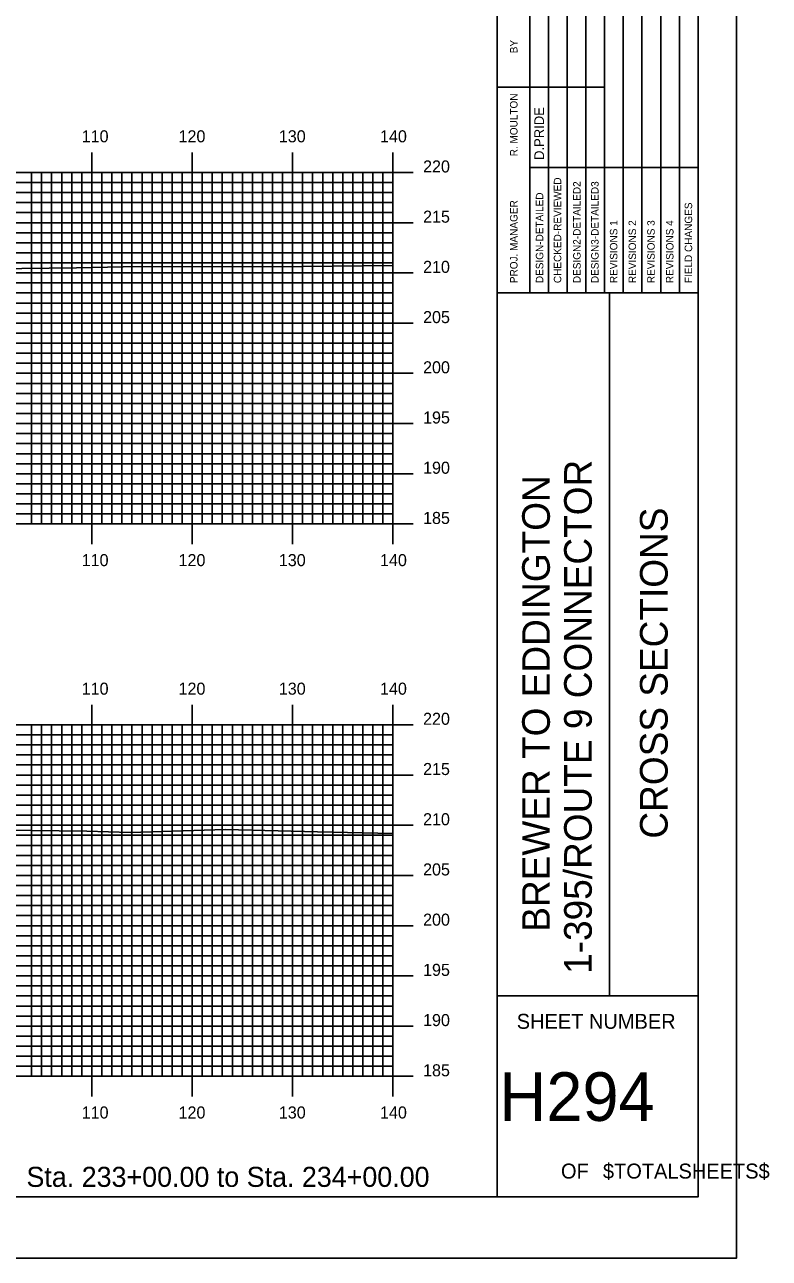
# Model space of a CAD drawing. Extents: x 1799962 to 1800305, y 442591 to 442811.
# Drawn here: x 1800230.8 to 1800305, y 442590.5 to 442713.4 of the extents above; entities that cross this region are included whole.
import ezdxf

# ---------------------------------------------------------------- set-up
doc = ezdxf.new("R2010")
doc.units = 0
for name, color, linetype in [('BORDER', 7, 'Continuous'), ('H_V ANNOTATION', 7, 'Continuous'), ('MAJOR', 7, 'Continuous'), ('MINOR', 7, 'Continuous'), ('PLOT BOUNDARY', 7, 'Continuous'), ('S_Roadway_Centerline', 7, 'Continuous')]:
    doc.layers.add(name, color=color, linetype=linetype)

msp = doc.modelspace()

# ---------------------------------------------------------------- linework, layer by layer
at = {"layer": 'BORDER'}
for p, q in [((1800277.92, 442596.67), (1800277.92, 442806.67)), ((1800277.92, 442686.67), (1800297.92, 442686.67)), ((1800289.11, 442616.67), (1800289.11, 442686.67)), ((1800277.92, 442616.67), (1800297.92, 442616.67))]:
    msp.add_line(p, q, dxfattribs=at)
msp.add_lwpolyline([(1799977.92, 442596.67), (1800297.92, 442596.67), (1800297.92, 442806.67), (1799977.92, 442806.67)], close=True, dxfattribs=at)
for points in [[(1800283.02, 442686.68), (1800283.02, 442721.67)], [(1800284.88, 442721.67), (1800284.88, 442686.68)], [(1800286.74, 442686.68), (1800286.74, 442721.67)], [(1800288.61, 442686.68), (1800288.61, 442721.67)], [(1800290.47, 442686.68), (1800290.47, 442721.67)], [(1800292.33, 442686.68), (1800292.33, 442721.67)], [(1800294.2, 442686.68), (1800294.2, 442721.67)], [(1800296.06, 442686.68), (1800296.06, 442721.67)], [(1800281.15, 442686.68), (1800281.15, 442720.26)], [(1800277.92, 442707.17), (1800281.15, 442707.17)], [(1800281.15, 442707.17), (1800288.61, 442707.17)], [(1800281.15, 442699.17), (1800297.92, 442699.17)]]:
    msp.add_lwpolyline(points, dxfattribs=at)
at = {"layer": 'MAJOR'}
for p, q in [((1800237.52, 442700.67), (1800237.52, 442698.67)), ((1800247.52, 442700.67), (1800247.52, 442698.67)), ((1800257.52, 442700.67), (1800257.52, 442698.67)), ((1800267.52, 442700.67), (1800267.52, 442698.67)), ((1799987.52, 442698.67), (1800267.52, 442698.67)), ((1799987.52, 442698.67), (1800267.52, 442698.67)), ((1800237.52, 442663.67), (1800237.52, 442698.67)), ((1800247.52, 442663.67), (1800247.52, 442698.67)), ((1800257.52, 442663.67), (1800257.52, 442698.67)), ((1800269.53, 442698.67), (1800265.52, 442698.67)), ((1800267.52, 442663.67), (1800267.52, 442698.67)), ((1800267.52, 442663.67), (1800267.52, 442698.67)), ((1799987.52, 442693.67), (1800267.52, 442693.67)), ((1800269.53, 442693.67), (1800265.52, 442693.67)), ((1799987.52, 442688.67), (1800267.52, 442688.67)), ((1800269.53, 442688.67), (1800265.52, 442688.67)), ((1799987.52, 442683.67), (1800267.52, 442683.67)), ((1800269.53, 442683.67), (1800265.52, 442683.67)), ((1799987.52, 442678.67), (1800267.52, 442678.67)), ((1800269.53, 442678.67), (1800265.52, 442678.67)), ((1799987.52, 442673.67), (1800267.52, 442673.67)), ((1800269.53, 442673.67), (1800265.52, 442673.67)), ((1799987.52, 442668.67), (1800267.52, 442668.67)), ((1800269.53, 442668.67), (1800265.52, 442668.67)), ((1799987.52, 442663.67), (1800267.52, 442663.67)), ((1799987.52, 442663.67), (1800267.52, 442663.67)), ((1800237.52, 442661.66), (1800237.52, 442663.67)), ((1800247.52, 442661.66), (1800247.52, 442663.67)), ((1800257.52, 442661.66), (1800257.52, 442663.67)), ((1800269.53, 442663.67), (1800265.52, 442663.67)), ((1800267.52, 442661.66), (1800267.52, 442663.67)), ((1800237.52, 442645.67), (1800237.52, 442643.67)), ((1800247.52, 442645.67), (1800247.52, 442643.67)), ((1800257.52, 442645.67), (1800257.52, 442643.67)), ((1800267.52, 442645.67), (1800267.52, 442643.67)), ((1799987.52, 442643.67), (1800267.52, 442643.67)), ((1799987.52, 442643.67), (1800267.52, 442643.67)), ((1800237.52, 442608.67), (1800237.52, 442643.67)), ((1800247.52, 442608.67), (1800247.52, 442643.67)), ((1800257.52, 442608.67), (1800257.52, 442643.67)), ((1800269.53, 442643.67), (1800265.52, 442643.67)), ((1800267.52, 442608.67), (1800267.52, 442643.67)), ((1800267.52, 442608.67), (1800267.52, 442643.67)), ((1799987.52, 442638.67), (1800267.52, 442638.67)), ((1800269.53, 442638.67), (1800265.52, 442638.67)), ((1799987.52, 442633.67), (1800267.52, 442633.67)), ((1800269.53, 442633.67), (1800265.52, 442633.67)), ((1799987.52, 442628.67), (1800267.52, 442628.67)), ((1800269.53, 442628.67), (1800265.52, 442628.67)), ((1799987.52, 442623.67), (1800267.52, 442623.67)), ((1800269.53, 442623.67), (1800265.52, 442623.67)), ((1799987.52, 442618.67), (1800267.52, 442618.67)), ((1800269.53, 442618.67), (1800265.52, 442618.67)), ((1799987.52, 442613.67), (1800267.52, 442613.67)), ((1800269.53, 442613.67), (1800265.52, 442613.67)), ((1799987.52, 442608.67), (1800267.52, 442608.67)), ((1799987.52, 442608.67), (1800267.52, 442608.67)), ((1800237.52, 442606.66), (1800237.52, 442608.67)), ((1800247.52, 442606.66), (1800247.52, 442608.67)), ((1800257.52, 442606.66), (1800257.52, 442608.67)), ((1800269.53, 442608.67), (1800265.52, 442608.67)), ((1800267.52, 442606.66), (1800267.52, 442608.67))]:
    msp.add_line(p, q, dxfattribs=at)
at = {"layer": 'MINOR'}
for p, q in [((1800231.52, 442663.67), (1800231.52, 442698.67)), ((1800232.52, 442663.67), (1800232.52, 442698.67)), ((1800233.52, 442663.67), (1800233.52, 442698.67)), ((1800234.52, 442663.67), (1800234.52, 442698.67)), ((1800235.52, 442663.67), (1800235.52, 442698.67)), ((1800236.52, 442663.67), (1800236.52, 442698.67)), ((1800238.52, 442663.67), (1800238.52, 442698.67)), ((1800239.52, 442663.67), (1800239.52, 442698.67)), ((1800240.52, 442663.67), (1800240.52, 442698.67)), ((1800241.52, 442663.67), (1800241.52, 442698.67)), ((1800242.52, 442663.67), (1800242.52, 442698.67)), ((1800243.52, 442663.67), (1800243.52, 442698.67)), ((1800244.52, 442663.67), (1800244.52, 442698.67)), ((1800245.52, 442663.67), (1800245.52, 442698.67)), ((1800246.52, 442663.67), (1800246.52, 442698.67)), ((1800248.52, 442663.67), (1800248.52, 442698.67)), ((1800249.52, 442663.67), (1800249.52, 442698.67)), ((1800250.52, 442663.67), (1800250.52, 442698.67)), ((1800251.52, 442663.67), (1800251.52, 442698.67)), ((1800252.52, 442663.67), (1800252.52, 442698.67)), ((1800253.52, 442663.67), (1800253.52, 442698.67)), ((1800254.52, 442663.67), (1800254.52, 442698.67)), ((1800255.52, 442663.67), (1800255.52, 442698.67)), ((1800256.52, 442663.67), (1800256.52, 442698.67)), ((1800258.52, 442663.67), (1800258.52, 442698.67)), ((1800259.52, 442663.67), (1800259.52, 442698.67)), ((1800260.52, 442663.67), (1800260.52, 442698.67)), ((1800261.52, 442663.67), (1800261.52, 442698.67)), ((1800262.52, 442663.67), (1800262.52, 442698.67)), ((1800263.52, 442663.67), (1800263.52, 442698.67)), ((1800264.52, 442663.67), (1800264.52, 442698.67)), ((1800265.52, 442663.67), (1800265.52, 442698.67)), ((1800266.52, 442663.67), (1800266.52, 442698.67)), ((1799987.52, 442697.67), (1800267.52, 442697.67)), ((1800267.52, 442697.67), (1800265.52, 442697.67)), ((1799987.52, 442696.67), (1800267.52, 442696.67)), ((1800267.52, 442696.67), (1800265.52, 442696.67)), ((1799987.52, 442695.67), (1800267.52, 442695.67)), ((1800267.52, 442695.67), (1800265.52, 442695.67)), ((1799987.52, 442694.67), (1800267.52, 442694.67)), ((1800267.52, 442694.67), (1800265.52, 442694.67)), ((1799987.52, 442692.67), (1800267.52, 442692.67)), ((1800267.52, 442692.67), (1800265.52, 442692.67)), ((1799987.52, 442691.67), (1800267.52, 442691.67)), ((1800267.52, 442691.67), (1800265.52, 442691.67)), ((1799987.52, 442690.67), (1800267.52, 442690.67)), ((1800267.52, 442690.67), (1800265.52, 442690.67)), ((1799987.52, 442689.67), (1800267.52, 442689.67)), ((1800267.52, 442689.67), (1800265.52, 442689.67)), ((1799987.52, 442687.67), (1800267.52, 442687.67)), ((1800267.52, 442687.67), (1800265.52, 442687.67)), ((1799987.52, 442686.67), (1800267.52, 442686.67)), ((1800267.52, 442686.67), (1800265.52, 442686.67)), ((1799987.52, 442685.67), (1800267.52, 442685.67)), ((1800267.52, 442685.67), (1800265.52, 442685.67)), ((1799987.52, 442684.67), (1800267.52, 442684.67)), ((1800267.52, 442684.67), (1800265.52, 442684.67)), ((1799987.52, 442682.67), (1800267.52, 442682.67)), ((1800267.52, 442682.67), (1800265.52, 442682.67)), ((1799987.52, 442681.67), (1800267.52, 442681.67)), ((1800267.52, 442681.67), (1800265.52, 442681.67)), ((1799987.52, 442680.67), (1800267.52, 442680.67)), ((1800267.52, 442680.67), (1800265.52, 442680.67)), ((1799987.52, 442679.67), (1800267.52, 442679.67)), ((1800267.52, 442679.67), (1800265.52, 442679.67)), ((1799987.52, 442677.67), (1800267.52, 442677.67)), ((1799987.52, 442676.67), (1800267.52, 442676.67)), ((1800267.52, 442677.67), (1800265.52, 442677.67)), ((1800267.52, 442676.67), (1800265.52, 442676.67)), ((1799987.52, 442675.67), (1800267.52, 442675.67)), ((1800267.52, 442675.67), (1800265.52, 442675.67)), ((1799987.52, 442674.67), (1800267.52, 442674.67)), ((1800267.52, 442674.67), (1800265.52, 442674.67)), ((1799987.52, 442672.67), (1800267.52, 442672.67)), ((1799987.52, 442671.67), (1800267.52, 442671.67)), ((1800267.52, 442672.67), (1800265.52, 442672.67)), ((1800267.52, 442671.67), (1800265.52, 442671.67)), ((1799987.52, 442670.67), (1800267.52, 442670.67)), ((1800267.52, 442670.67), (1800265.52, 442670.67)), ((1799987.52, 442669.67), (1800267.52, 442669.67)), ((1800267.52, 442669.67), (1800265.52, 442669.67)), ((1799987.52, 442667.67), (1800267.52, 442667.67)), ((1799987.52, 442666.67), (1800267.52, 442666.67)), ((1800267.52, 442667.67), (1800265.52, 442667.67)), ((1800267.52, 442666.67), (1800265.52, 442666.67)), ((1799987.52, 442665.67), (1800267.52, 442665.67)), ((1800267.52, 442665.67), (1800265.52, 442665.67)), ((1799987.52, 442664.67), (1800267.52, 442664.67)), ((1800267.52, 442664.67), (1800265.52, 442664.67)), ((1800231.52, 442608.67), (1800231.52, 442643.67)), ((1800232.52, 442608.67), (1800232.52, 442643.67)), ((1800233.52, 442608.67), (1800233.52, 442643.67)), ((1800234.52, 442608.67), (1800234.52, 442643.67)), ((1800235.52, 442608.67), (1800235.52, 442643.67)), ((1800236.52, 442608.67), (1800236.52, 442643.67)), ((1800238.52, 442608.67), (1800238.52, 442643.67)), ((1800239.52, 442608.67), (1800239.52, 442643.67)), ((1800240.52, 442608.67), (1800240.52, 442643.67)), ((1800241.52, 442608.67), (1800241.52, 442643.67)), ((1800242.52, 442608.67), (1800242.52, 442643.67)), ((1800243.52, 442608.67), (1800243.52, 442643.67)), ((1800244.52, 442608.67), (1800244.52, 442643.67)), ((1800245.52, 442608.67), (1800245.52, 442643.67)), ((1800246.52, 442608.67), (1800246.52, 442643.67)), ((1800248.52, 442608.67), (1800248.52, 442643.67)), ((1800249.52, 442608.67), (1800249.52, 442643.67)), ((1800250.52, 442608.67), (1800250.52, 442643.67)), ((1800251.52, 442608.67), (1800251.52, 442643.67)), ((1800252.52, 442608.67), (1800252.52, 442643.67)), ((1800253.52, 442608.67), (1800253.52, 442643.67)), ((1800254.52, 442608.67), (1800254.52, 442643.67)), ((1800255.52, 442608.67), (1800255.52, 442643.67)), ((1800256.52, 442608.67), (1800256.52, 442643.67)), ((1800258.52, 442608.67), (1800258.52, 442643.67)), ((1800259.52, 442608.67), (1800259.52, 442643.67)), ((1800260.52, 442608.67), (1800260.52, 442643.67)), ((1800261.52, 442608.67), (1800261.52, 442643.67)), ((1800262.52, 442608.67), (1800262.52, 442643.67)), ((1800263.52, 442608.67), (1800263.52, 442643.67)), ((1800264.52, 442608.67), (1800264.52, 442643.67)), ((1800265.52, 442608.67), (1800265.52, 442643.67)), ((1800266.52, 442608.67), (1800266.52, 442643.67)), ((1799987.52, 442642.67), (1800267.52, 442642.67)), ((1800267.52, 442642.67), (1800265.52, 442642.67)), ((1799987.52, 442641.67), (1800267.52, 442641.67)), ((1800267.52, 442641.67), (1800265.52, 442641.67)), ((1799987.52, 442640.67), (1800267.52, 442640.67)), ((1799987.52, 442639.67), (1800267.52, 442639.67)), ((1800267.52, 442640.67), (1800265.52, 442640.67)), ((1800267.52, 442639.67), (1800265.52, 442639.67)), ((1799987.52, 442637.67), (1800267.52, 442637.67)), ((1800267.52, 442637.67), (1800265.52, 442637.67)), ((1799987.52, 442636.67), (1800267.52, 442636.67)), ((1800267.52, 442636.67), (1800265.52, 442636.67)), ((1799987.52, 442635.67), (1800267.52, 442635.67)), ((1800267.52, 442635.67), (1800265.52, 442635.67)), ((1799987.52, 442634.67), (1800267.52, 442634.67)), ((1800267.52, 442634.67), (1800265.52, 442634.67)), ((1799987.52, 442632.67), (1800267.52, 442632.67)), ((1800267.52, 442632.67), (1800265.52, 442632.67)), ((1799987.52, 442631.67), (1800267.52, 442631.67)), ((1800267.52, 442631.67), (1800265.52, 442631.67)), ((1799987.52, 442630.67), (1800267.52, 442630.67)), ((1800267.52, 442630.67), (1800265.52, 442630.67)), ((1799987.52, 442629.67), (1800267.52, 442629.67)), ((1800267.52, 442629.67), (1800265.52, 442629.67)), ((1799987.52, 442627.67), (1800267.52, 442627.67)), ((1800267.52, 442627.67), (1800265.52, 442627.67)), ((1799987.52, 442626.67), (1800267.52, 442626.67)), ((1800267.52, 442626.67), (1800265.52, 442626.67)), ((1799987.52, 442625.67), (1800267.52, 442625.67)), ((1800267.52, 442625.67), (1800265.52, 442625.67)), ((1799987.52, 442624.67), (1800267.52, 442624.67)), ((1800267.52, 442624.67), (1800265.52, 442624.67)), ((1799987.52, 442622.67), (1800267.52, 442622.67)), ((1800267.52, 442622.67), (1800265.52, 442622.67)), ((1799987.52, 442621.67), (1800267.52, 442621.67)), ((1800267.52, 442621.67), (1800265.52, 442621.67)), ((1799987.52, 442620.67), (1800267.52, 442620.67)), ((1800267.52, 442620.67), (1800265.52, 442620.67)), ((1799987.52, 442619.67), (1800267.52, 442619.67)), ((1800267.52, 442619.67), (1800265.52, 442619.67)), ((1799987.52, 442617.67), (1800267.52, 442617.67)), ((1800267.52, 442617.67), (1800265.52, 442617.67)), ((1799987.52, 442616.67), (1800267.52, 442616.67)), ((1800267.52, 442616.67), (1800265.52, 442616.67)), ((1799987.52, 442615.67), (1800267.52, 442615.67)), ((1800267.52, 442615.67), (1800265.52, 442615.67)), ((1799987.52, 442614.67), (1800267.52, 442614.67)), ((1800267.52, 442614.67), (1800265.52, 442614.67)), ((1799987.52, 442612.67), (1800267.52, 442612.67)), ((1800267.52, 442612.67), (1800265.52, 442612.67)), ((1799987.52, 442611.67), (1800267.52, 442611.67)), ((1800267.52, 442611.67), (1800265.52, 442611.67)), ((1799987.52, 442610.67), (1800267.52, 442610.67)), ((1800267.52, 442610.67), (1800265.52, 442610.67)), ((1799987.52, 442609.67), (1800267.52, 442609.67)), ((1800267.52, 442609.67), (1800265.52, 442609.67))]:
    msp.add_line(p, q, dxfattribs=at)
at = {"layer": 'PLOT BOUNDARY'}
msp.add_lwpolyline([(1799961.74, 442590.55), (1800301.74, 442590.55), (1800301.74, 442810.55), (1799961.74, 442810.55)], close=True, dxfattribs=at)
at = {"layer": 'S_Roadway_Centerline'}
for points in [[(1800144.2, 442689.77), (1800163.19, 442690.31), (1800168.12, 442690.26), (1800172.58, 442690.24), (1800179.53, 442689.82), (1800187.51, 442689.59), (1800191.53, 442689.49), (1800211.8, 442689.03), (1800214.69, 442689), (1800216.87, 442688.95), (1800236.01, 442689.19), (1800240.63, 442689.27), (1800258.56, 442689.3), (1800261.59, 442689.34), (1800267.52, 442689.42)], [(1800157.96, 442633.42), (1800167.23, 442633.22), (1800171.02, 442633.19), (1800181.54, 442633.35), (1800192.26, 442633.27), (1800204.66, 442633.31), (1800215.54, 442633.22), (1800217.61, 442633.3), (1800237.01, 442633.08), (1800241.34, 442632.94), (1800250.84, 442633.25), (1800259.99, 442633.03), (1800267.52, 442632.85)]]:
    msp.add_lwpolyline(points, dxfattribs=at)

# ---------------------------------------------------------------- texts
at = {"layer": 'BORDER'}
for s, height, p in [('BY', 0.743, (1800279.93, 442710.54)), ('R. MOULTON', 0.745, (1800279.93, 442700.28)), ('D.PRIDE', 0.969, (1800282.57, 442699.92)), ('CHECKED-REVIEWED', 0.7455, (1800284.29, 442687.65)), ('DESIGN2-DETAILED2', 0.7455, (1800286.22, 442687.65)), ('DESIGN3-DETAILED3', 0.7455, (1800288.01, 442687.65)), ('DESIGN-DETAILED', 0.7455, (1800282.5, 442687.65)), ('PROJ. MANAGER', 0.7455, (1800279.93, 442687.65)), ('FIELD CHANGES', 0.7455, (1800297.33, 442687.65)), ('REVISIONS 1', 0.7455, (1800289.88, 442687.65)), ('REVISIONS 2', 0.7455, (1800291.74, 442687.65)), ('REVISIONS 3', 0.7455, (1800293.6, 442687.65)), ('REVISIONS 4', 0.7455, (1800295.47, 442687.65)), ('1-395/ROUTE 9 CONNECTOR', 2.7557, (1800287.33, 442618.87)), ('BREWER TO EDDINGTON', 2.7557, (1800283.15, 442623.07)), ('CROSS SECTIONS', 2.7557, (1800294.89, 442632.34))]:
    msp.add_text(s, height=height, rotation=90, dxfattribs=at).set_placement(p)
for s, height, p in [('SHEET NUMBER', 1.4905, (1800279.85, 442613.4)), ('H294', 4.839, (1800278.13, 442604.23)), ('OF', 1.491, (1800284.26, 442598.49)), ('$TOTALSHEETS$', 1.4905, (1800288.44, 442598.49))]:
    msp.add_text(s, height=height, dxfattribs=at).set_placement(p)
at = {"layer": 'H_V ANNOTATION'}
for s, height, p in [('110', 1.2, (1800236.51, 442701.67)), ('120', 1.2, (1800246.16, 442701.67)), ('130', 1.2, (1800256.15, 442701.67)), ('140', 1.2, (1800266.23, 442701.67)), ('220', 1.2, (1800270.52, 442698.67)), ('215', 1.2, (1800270.52, 442693.67)), ('210', 1.2, (1800270.52, 442688.67)), ('205', 1.2, (1800270.52, 442683.67)), ('200', 1.2, (1800270.52, 442678.67)), ('195', 1.2, (1800270.52, 442673.67)), ('190', 1.2, (1800270.52, 442668.67)), ('185', 1.2, (1800270.52, 442663.67)), ('110', 1.2, (1800236.51, 442659.47)), ('120', 1.2, (1800246.16, 442659.47)), ('130', 1.2, (1800256.15, 442659.47)), ('140', 1.2, (1800266.23, 442659.47)), ('110', 1.2, (1800236.51, 442646.67)), ('120', 1.2, (1800246.16, 442646.67)), ('130', 1.2, (1800256.15, 442646.67)), ('140', 1.2, (1800266.23, 442646.67)), ('220', 1.2, (1800270.52, 442643.67)), ('215', 1.2, (1800270.52, 442638.67)), ('210', 1.2, (1800270.52, 442633.67)), ('205', 1.2, (1800270.52, 442628.67)), ('200', 1.2, (1800270.52, 442623.67)), ('195', 1.2, (1800270.52, 442618.67)), ('190', 1.2, (1800270.52, 442613.67)), ('185', 1.2, (1800270.52, 442608.67)), ('110', 1.2, (1800236.51, 442604.47)), ('120', 1.2, (1800246.16, 442604.47)), ('130', 1.2, (1800256.15, 442604.47)), ('140', 1.2, (1800266.23, 442604.47)), ('Sta. 233+00.00 to Sta. 234+00.00', 2.0004, (1800231.01, 442597.66))]:
    msp.add_text(s, height=height, dxfattribs=at).set_placement(p)

doc.saveas('drawing.dxf')
